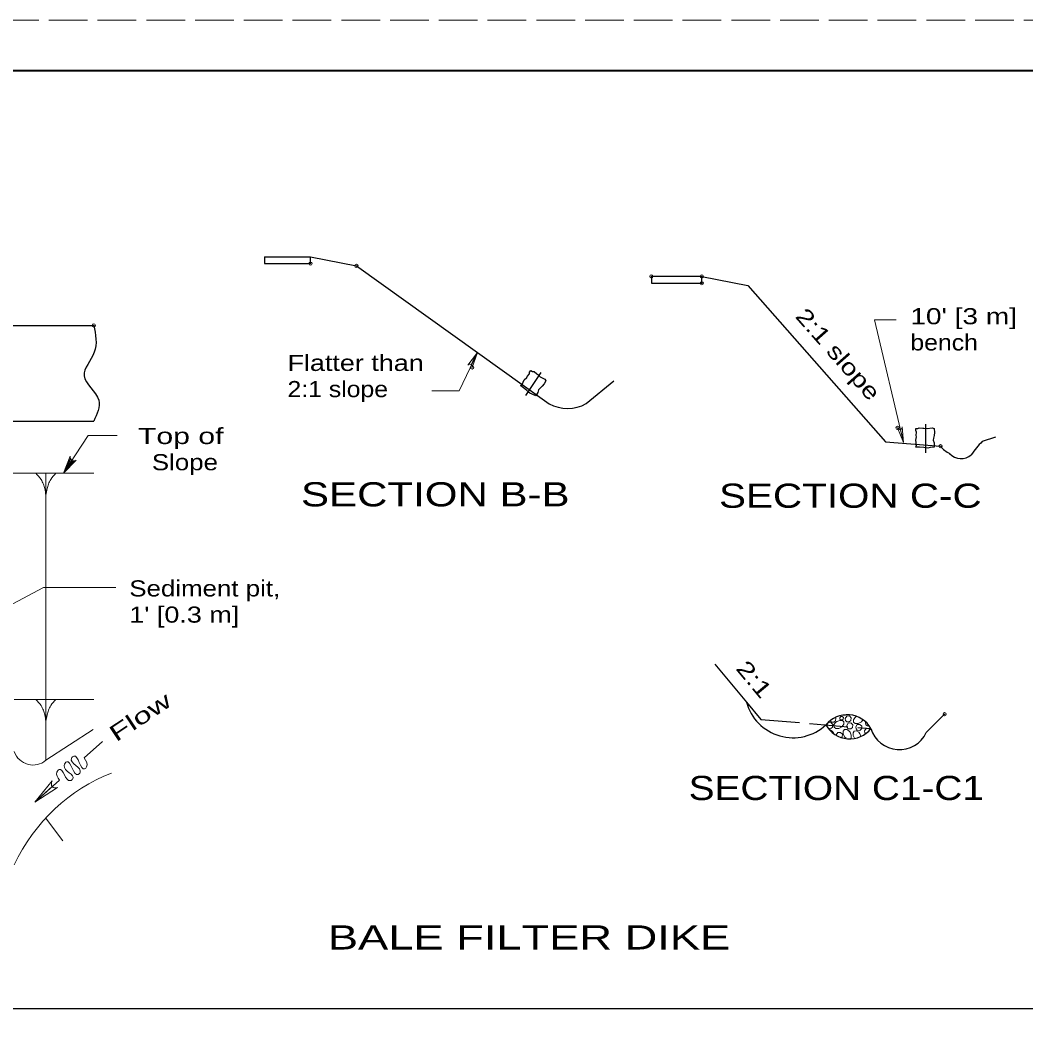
# Model space of a CAD drawing. Extents: x 1043.1 to 1101.1, y 672.4 to 716.4.
# Drawn here: x 1055.66 to 1065.65, y 706.48 to 716.4 of the extents above; entities that cross this region are included whole.
import ezdxf
from ezdxf.enums import TextEntityAlignment as Align

# ---------------------------------------------------------------- set-up
doc = ezdxf.new("R2010")
doc.units = 0
doc.header["$LTSCALE"] = 0.064
doc.header["$PDMODE"] = 32
doc.header["$PDSIZE"] = 0.032
doc.linetypes.add('LONG_DASHED', pattern=[7.5, 6, -1.5])
doc.layers.add('1', color=7, linetype='Continuous', lineweight=13)

msp = doc.modelspace()

# ---------------------------------------------------------------- linework, layer by layer
at = {"layer": '1', "lineweight": 25}
for p, q in [((1045.14425, 715.89508), (1076.64425, 715.89508)), ((1058.54592, 713.97767), (1058.54592, 714.04608)), ((1059.00167, 713.95483), (1060.916, 712.58767)), ((1062.43142, 713.851), (1061.93008, 713.851)), ((1061.93008, 713.851), (1061.93008, 713.78267)), ((1061.93008, 713.78267), (1062.43142, 713.78267)), ((1062.43142, 713.78267), (1062.43142, 713.851)), ((1047.132, 713.36458), (1056.394, 713.36458)), ((1060.68367, 712.66908), (1060.83675, 712.89558)), ((1061.28242, 712.588), (1061.55592, 712.81583)), ((1047.132, 712.41483), (1056.394, 712.41483)), ((1064.65275, 712.38275), (1064.65275, 712.09833)), ((1065.34842, 712.25592), (1065.21392, 712.21308)), ((1062.56092, 710.00017), (1062.87383, 709.62467)), ((1064.65933, 709.32283), (1064.84167, 709.50517)), ((1045.14425, 706.58517), (1075.64425, 706.58517))]:
    msp.add_line(p, q, dxfattribs=at)
at = {"layer": '1', "lineweight": 40}
msp.add_line((1045.14425, 715.89508), (1076.64425, 715.89508), dxfattribs=at)
at = {"layer": '1'}
for p, q in [((1060.13967, 712.9775), (1060.20383, 713.09633)), ((1060.15825, 713.01183), (1060.20383, 713.09633)), ((1064.403, 712.33258), (1064.43392, 712.20117)), ((1064.412, 712.29467), (1064.43392, 712.20117)), ((1056.16183, 712.04725), (1056.094, 711.89675)), ((1056.16725, 712.03633), (1056.094, 711.89675)), ((1056.17783, 712.02608), (1056.094, 711.89675)), ((1056.18833, 712.02125), (1056.094, 711.89675)), ((1056.20067, 712.01975), (1056.094, 711.89675)), ((1056.17492, 712.0215), (1056.09525, 711.89858)), ((1047.132, 711.89675), (1056.394, 711.89675)), ((1055.82008, 711.89675), (1056.018, 711.89675)), ((1055.82008, 711.89675), (1056.018, 711.89675)), ((1055.919, 710.16542), (1055.919, 711.89675)), ((1055.919, 709.6515), (1055.919, 710.16542)), ((1056.394, 709.6515), (1055.6025, 709.6515)), ((1055.82008, 709.6515), (1056.018, 709.6515)), ((1055.919, 709.04725), (1055.919, 709.6515)), ((1063.9635, 709.48117), (1063.96425, 709.4815)), ((1063.67042, 709.39758), (1063.683, 709.41575)), ((1063.67308, 709.3835), (1063.67042, 709.39758)), ((1055.919, 709.04725), (1056.38808, 709.3525)), ((1063.73708, 709.32283), (1063.74167, 709.3115)), ((1063.76642, 709.2995), (1063.76642, 709.29983)), ((1064.00008, 709.31192), (1064.00983, 709.2875)), ((1056.29825, 709.07033), (1056.48175, 709.23492)), ((1055.80858, 708.63233), (1056.0535, 708.85142)), ((1055.98067, 708.7865), (1055.80858, 708.63233)), ((1055.931, 708.74192), (1055.80858, 708.63233)), ((1055.91608, 708.47575), (1056.08792, 708.24683))]:
    msp.add_line(p, q, dxfattribs=at)
at = {"layer": '1', "linetype": 'LONG_DASHED', "lineweight": 25}
for p, q in [((1062.87383, 709.62467), (1063.01667, 709.45317)), ((1063.01667, 709.45317), (1064.11058, 709.362))]:
    msp.add_line(p, q, dxfattribs=at)
at = {"layer": '1', "linetype": 'LONG_DASHED'}
msp.add_lwpolyline([(1043.14425, 694.39508), (1077.14425, 694.39508), (1077.14425, 716.39508), (1043.14425, 716.39508)], close=True, dxfattribs=at)
at = {"layer": '1', "lineweight": 40}
msp.add_lwpolyline([(1045.14425, 715.89508), (1076.64425, 715.89508), (1076.64425, 694.89508), (1045.14425, 694.89508)], close=True, dxfattribs=at)
at = {"layer": '1', "lineweight": 25}
for points in [[(1058.09008, 714.04608), (1058.54592, 714.04608), (1059.00167, 713.95483)], [(1058.09008, 714.04608), (1058.09008, 713.97767), (1058.54592, 713.97767)], [(1062.43142, 713.851), (1062.88717, 713.75983), (1064.2545, 712.21033), (1064.8015, 712.16475)], [(1060.62983, 712.76625), (1060.64608, 712.77867), (1060.66842, 712.82342), (1060.69225, 712.84792), (1060.69667, 712.85842), (1060.71967, 712.88508), (1060.72192, 712.90075), (1060.73208, 712.91792)], [(1060.73208, 712.91792), (1060.74925, 712.90783), (1060.765, 712.90558), (1060.79167, 712.88267), (1060.80217, 712.87825), (1060.82675, 712.85433), (1060.8715, 712.83192), (1060.88383, 712.81567)], [(1060.88383, 712.81567), (1060.86433, 712.78375), (1060.84658, 712.76042), (1060.82467, 712.74308), (1060.81125, 712.725), (1060.80342, 712.7), (1060.79375, 712.68108), (1060.78183, 712.66442)], [(1060.78183, 712.66442), (1060.74642, 712.68342), (1060.72442, 712.69117), (1060.71033, 712.70175), (1060.69383, 712.71725), (1060.66083, 712.74583), (1060.63033, 712.76642)], [(1064.55533, 712.33983), (1064.57525, 712.34117), (1064.5895, 712.348), (1064.6245, 712.34392), (1064.63567, 712.346), (1064.66942, 712.34), (1064.719, 712.34658), (1064.73833, 712.33992)], [(1064.55533, 712.157), (1064.56192, 712.17633), (1064.5555, 712.22592), (1064.5615, 712.25958), (1064.55925, 712.27067), (1064.56333, 712.30575), (1064.55658, 712.32), (1064.55533, 712.33983)], [(1064.73833, 712.33992), (1064.74, 712.30242), (1064.73833, 712.27325), (1064.72992, 712.24658), (1064.72883, 712.224), (1064.73642, 712.19908), (1064.73883, 712.178), (1064.73833, 712.15742)], [(1064.73833, 712.15742), (1064.69842, 712.15342), (1064.67575, 712.14758), (1064.65808, 712.14858), (1064.63575, 712.152), (1064.5925, 712.15742), (1064.55567, 712.15742)]]:
    msp.add_lwpolyline(points, dxfattribs=at)
at = {"layer": '1'}
for points in [[(1064.43392, 712.20117), (1064.146, 713.41933), (1064.36058, 713.41933)], [(1060.20383, 713.09633), (1060.02308, 712.71567), (1059.74917, 712.71567)], [(1060.10858, 712.97058), (1060.20383, 713.09633), (1060.15075, 712.94767)], [(1064.42167, 712.35842), (1064.43392, 712.20117), (1064.37483, 712.3475)], [(1056.62567, 712.27142), (1056.337, 712.27142), (1056.094, 711.89675)], [(1056.161, 712.06558), (1056.094, 711.89675), (1056.22083, 712.02683)], [(1054.27542, 709.90208), (1055.89358, 710.76142), (1056.61417, 710.76142)], [(1063.85775, 709.49717), (1063.85408, 709.49417), (1063.83225, 709.49583)], [(1064.03108, 709.45042), (1064.01483, 709.4295), (1063.9835, 709.41383), (1063.95408, 709.41342), (1063.93733, 709.42508), (1063.93583, 709.44867), (1063.94933, 709.46958), (1063.96425, 709.4815)], [(1063.68933, 709.421), (1063.71283, 709.42233), (1063.73092, 709.4035), (1063.72833, 709.37708), (1063.71217, 709.36375), (1063.69033, 709.36542)], [(1063.75625, 709.47067), (1063.76167, 709.46508), (1063.75908, 709.43858), (1063.74292, 709.42517), (1063.71725, 709.42708), (1063.70767, 709.43633)], [(1063.77042, 709.43133), (1063.80092, 709.4435), (1063.829, 709.44108), (1063.84242, 709.42842), (1063.84192, 709.40558), (1063.82175, 709.37958), (1063.79042, 709.364), (1063.761, 709.3635), (1063.74425, 709.37517), (1063.74267, 709.39883), (1063.75625, 709.41983), (1063.77167, 709.43225)], [(1064.0905, 709.3885), (1064.07575, 709.38817), (1064.05925, 709.4), (1064.05767, 709.42317)], [(1063.70458, 709.3505), (1063.7255, 709.337), (1063.73783, 709.32158)], [(1063.76642, 709.29983), (1063.78283, 709.323), (1063.809, 709.32433), (1063.827, 709.30575), (1063.8245, 709.27917), (1063.81942, 709.27517)], [(1063.86292, 709.26667), (1063.8515, 709.2755), (1063.83583, 709.30675), (1063.83542, 709.33617), (1063.84708, 709.35292), (1063.87067, 709.35442), (1063.89167, 709.34092), (1063.90392, 709.3255)], [(1063.90325, 709.32683), (1063.91533, 709.29625), (1063.91292, 709.26817), (1063.90908, 709.26417)], [(1063.94583, 709.266), (1063.93283, 709.292), (1063.93217, 709.3215), (1063.944, 709.338), (1063.96767, 709.3395), (1063.98858, 709.32617), (1064.00092, 709.31067)], [(1064.04658, 709.33917), (1064.06292, 709.3625), (1064.089, 709.364), (1064.10008, 709.35258)], [(1064.05508, 709.31467), (1064.05058, 709.31908), (1064.04658, 709.33917)], [(1056.03267, 708.77675), (1055.80858, 708.63233), (1055.9825, 708.84375), (1055.9825, 708.84358)]]:
    msp.add_lwpolyline(points, dxfattribs=at)
for points in [[(1063.80033, 709.46867), (1063.81, 709.4825), (1063.82567, 709.48342), (1063.83667, 709.47217), (1063.83508, 709.45633), (1063.82533, 709.44833), (1063.80992, 709.44942), (1063.80258, 709.4565)], [(1063.85375, 709.46258), (1063.87017, 709.48583), (1063.89633, 709.48742), (1063.91442, 709.4685), (1063.91183, 709.44225), (1063.89567, 709.42875), (1063.86992, 709.43075), (1063.85775, 709.44242)], [(1063.86933, 709.39308), (1063.8855, 709.41625), (1063.91167, 709.41783), (1063.92975, 709.399), (1063.92725, 709.3725), (1063.911, 709.35917), (1063.88533, 709.361), (1063.87325, 709.37283)], [(1063.95867, 709.37875), (1063.97492, 709.402), (1064.001, 709.4035), (1064.01908, 709.38467), (1064.0165, 709.35842), (1064.00042, 709.34492), (1063.97458, 709.34683), (1063.96258, 709.35858)]]:
    msp.add_lwpolyline(points, close=True, dxfattribs=at)
msp.add_arc((1056.19879, 712.05824), 0.03845, 169.11956, 304.94568, dxfattribs=at)
at = {"layer": '1', "lineweight": 25}
for centre, radius, start, end in [((1063.87456, 709.2296), 0.27062, 29.30429, 141.1631), ((1063.89965, 709.53053), 0.26993, 209.08639, 321.38099)]:
    msp.add_arc(centre, radius, start, end, dxfattribs=at)
at = {"layer": '1'}
for centre, major_axis, ratio, start_param, end_param in [((1060.12368, 712.94798), (0.016, 0.02961), 0.769152, 5.0978539, 7.4684671), ((1064.39533, 712.36526), (0.0077, -0.03276), 0.769152, 5.0978539, 7.4684671), ((1055.79204, 709.22703), (0, 0.22702), 0.916763, 1.9953194, 3.7979087), ((1057.14583, 707.12282), (0, -1.90348), 0.916763, 3.4772218, 4.2269565), ((1056.02365, 708.82474), (-0.03789, -0.04383), 0.770902, 4.9325066, 7.3031197)]:
    msp.add_ellipse(centre, major_axis=major_axis, ratio=ratio, start_param=start_param, end_param=end_param, dxfattribs=at)
at = {"layer": '1', "lineweight": 25}
for centre, major_axis, start_param, end_param in [((1061.09891, 712.92312), (-0.38212, 0), 1.0715367, 2.0717144), ((1066.5034, 711.05937), (-1.73034, 0), 5.5532488, 5.6520048), ((1065.01456, 712.34145), (-0.27679, 0), 0.6924119, 1.1126544), ((1065.00543, 712.19807), (-0.15517, 0), 0.7486776, 2.2798795), ((1063.33728, 709.75194), (-0.48062, 0), 0.2681175, 2.3176485), ((1064.39247, 709.44787), (-0.29469, 0), 0.2955473, 2.7034304)]:
    msp.add_ellipse(centre, major_axis=major_axis, ratio=0.999895, start_param=start_param, end_param=end_param, dxfattribs=at)
msp.add_spline([(1056.394, 713.36458), (1056.39892, 713.09733), (1056.29808, 712.86533), (1056.4435, 712.62083), (1056.394, 712.41483)], degree=3, dxfattribs=at)
at = {"layer": '1'}
for points in [[(1055.919, 711.68092), (1055.90725, 711.74358), (1055.894, 711.78875), (1055.8705, 711.836), (1055.82008, 711.89675)], [(1055.919, 711.68092), (1055.90725, 711.74358), (1055.894, 711.78875), (1055.8705, 711.836), (1055.82008, 711.89675)], [(1056.018, 711.89675), (1055.9675, 711.836), (1055.94425, 711.78875), (1055.93092, 711.74358), (1055.919, 711.68092)], [(1056.018, 711.89675), (1055.9675, 711.836), (1055.94425, 711.78875), (1055.93092, 711.74358), (1055.919, 711.68092)], [(1055.919, 709.43583), (1055.90725, 709.4985), (1055.894, 709.5435), (1055.8705, 709.59092), (1055.82008, 709.6515)], [(1056.018, 709.6515), (1055.9675, 709.59092), (1055.94425, 709.5435), (1055.93092, 709.4985), (1055.919, 709.43583)], [(1056.0535, 708.85142), (1056.02875, 708.93108), (1056.05125, 708.9575), (1056.161, 708.84558), (1056.18692, 708.86375), (1056.09942, 708.99558), (1056.12525, 709.03383), (1056.23808, 708.90683), (1056.25825, 708.92633), (1056.17208, 709.06692), (1056.19517, 709.08892), (1056.30317, 708.96242), (1056.32308, 708.98175), (1056.29825, 709.07033)]]:
    msp.add_spline(points, degree=3, dxfattribs=at)
for p in [(1058.54592, 713.97767), (1059.00167, 713.95483), (1061.93008, 713.851), (1062.43142, 713.851), (1062.43142, 713.78267), (1056.394, 713.36458), (1060.15075, 712.94767), (1064.37483, 712.3475), (1064.8015, 712.16475), (1064.84167, 709.50517)]:
    msp.add_point(p, dxfattribs=at)

# ---------------------------------------------------------------- texts
at = {"layer": '1', "width": 1.3}
msp.add_text('2:1 slope', height=0.16, rotation=311.427, dxfattribs=at).set_placement((1063.72424, 713.02627), align=Align.CENTER)
at = {"layer": '1'}
for s, height, width, p in [("10' [3 m]", 0.16, 1.3, (1064.50167, 713.37575)), ('bench', 0.16, 1.15, (1064.50167, 713.11575)), ('Flatter than', 0.16, 1.25, (1058.31742, 712.91242)), ('2:1 slope', 0.16, 1.15, (1058.31742, 712.65242)), ('Sediment pit,', 0.16, 1.2, (1056.74692, 710.67383)), ("1' [0.3 m]", 0.16, 1.25, (1056.74692, 710.41383)), ('BALE FILTER DIKE', 0.24, 1.4, (1058.71842, 707.16925))]:
    msp.add_text(s, height=height, dxfattribs=dict(at, width=width)).set_placement(p)
for s, height, width, p in [('Top of ', 0.16, 1.4, (1057.29908, 712.18667)), ('Slope', 0.16, 1.2, (1057.29904, 711.92667)), ('SECTION B-B', 0.24, 1.3, (1059.78471, 711.56792)), ('SECTION C-C', 0.24, 1.25, (1063.90579, 711.554)), ('SECTION C1-C1', 0.24, 1.2, (1063.76642, 708.65283))]:
    msp.add_text(s, height=height, dxfattribs=dict(at, width=width)).set_placement(p, align=Align.CENTER)
for s, rotation, width, p in [('2:1', 309.809, 1.35, (1062.76133, 709.9555)), ('Flow', 33.592, 1.5, (1056.61667, 709.22517))]:
    msp.add_text(s, height=0.16, rotation=rotation, dxfattribs=dict(at, width=width)).set_placement(p)

doc.saveas('drawing.dxf')
